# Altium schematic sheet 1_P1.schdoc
size 391 x 276 mm; Symbol: Drawing-Symbol_A4; Device: Drawing-Symbol_A4; Company: 嘉立创EDA; Version: V1.0; Page Size: A4; @Project Name: AD采集模组; @Page Count: 1; @Update Date: 2025-09-16; @Create Date: 2025-08-20; @Schematic Name: Schematic1; @Page No: 1; @Page Name: P1; @Create Time: 00:28:39; @Update Time: 18:31:51; Width: 1500; Height: 1058; Region Start: 1; X Region Count: 6; Y Region Count: 4; Blade Width: 10; Title Block Position: 3; @Board Name: AD采集
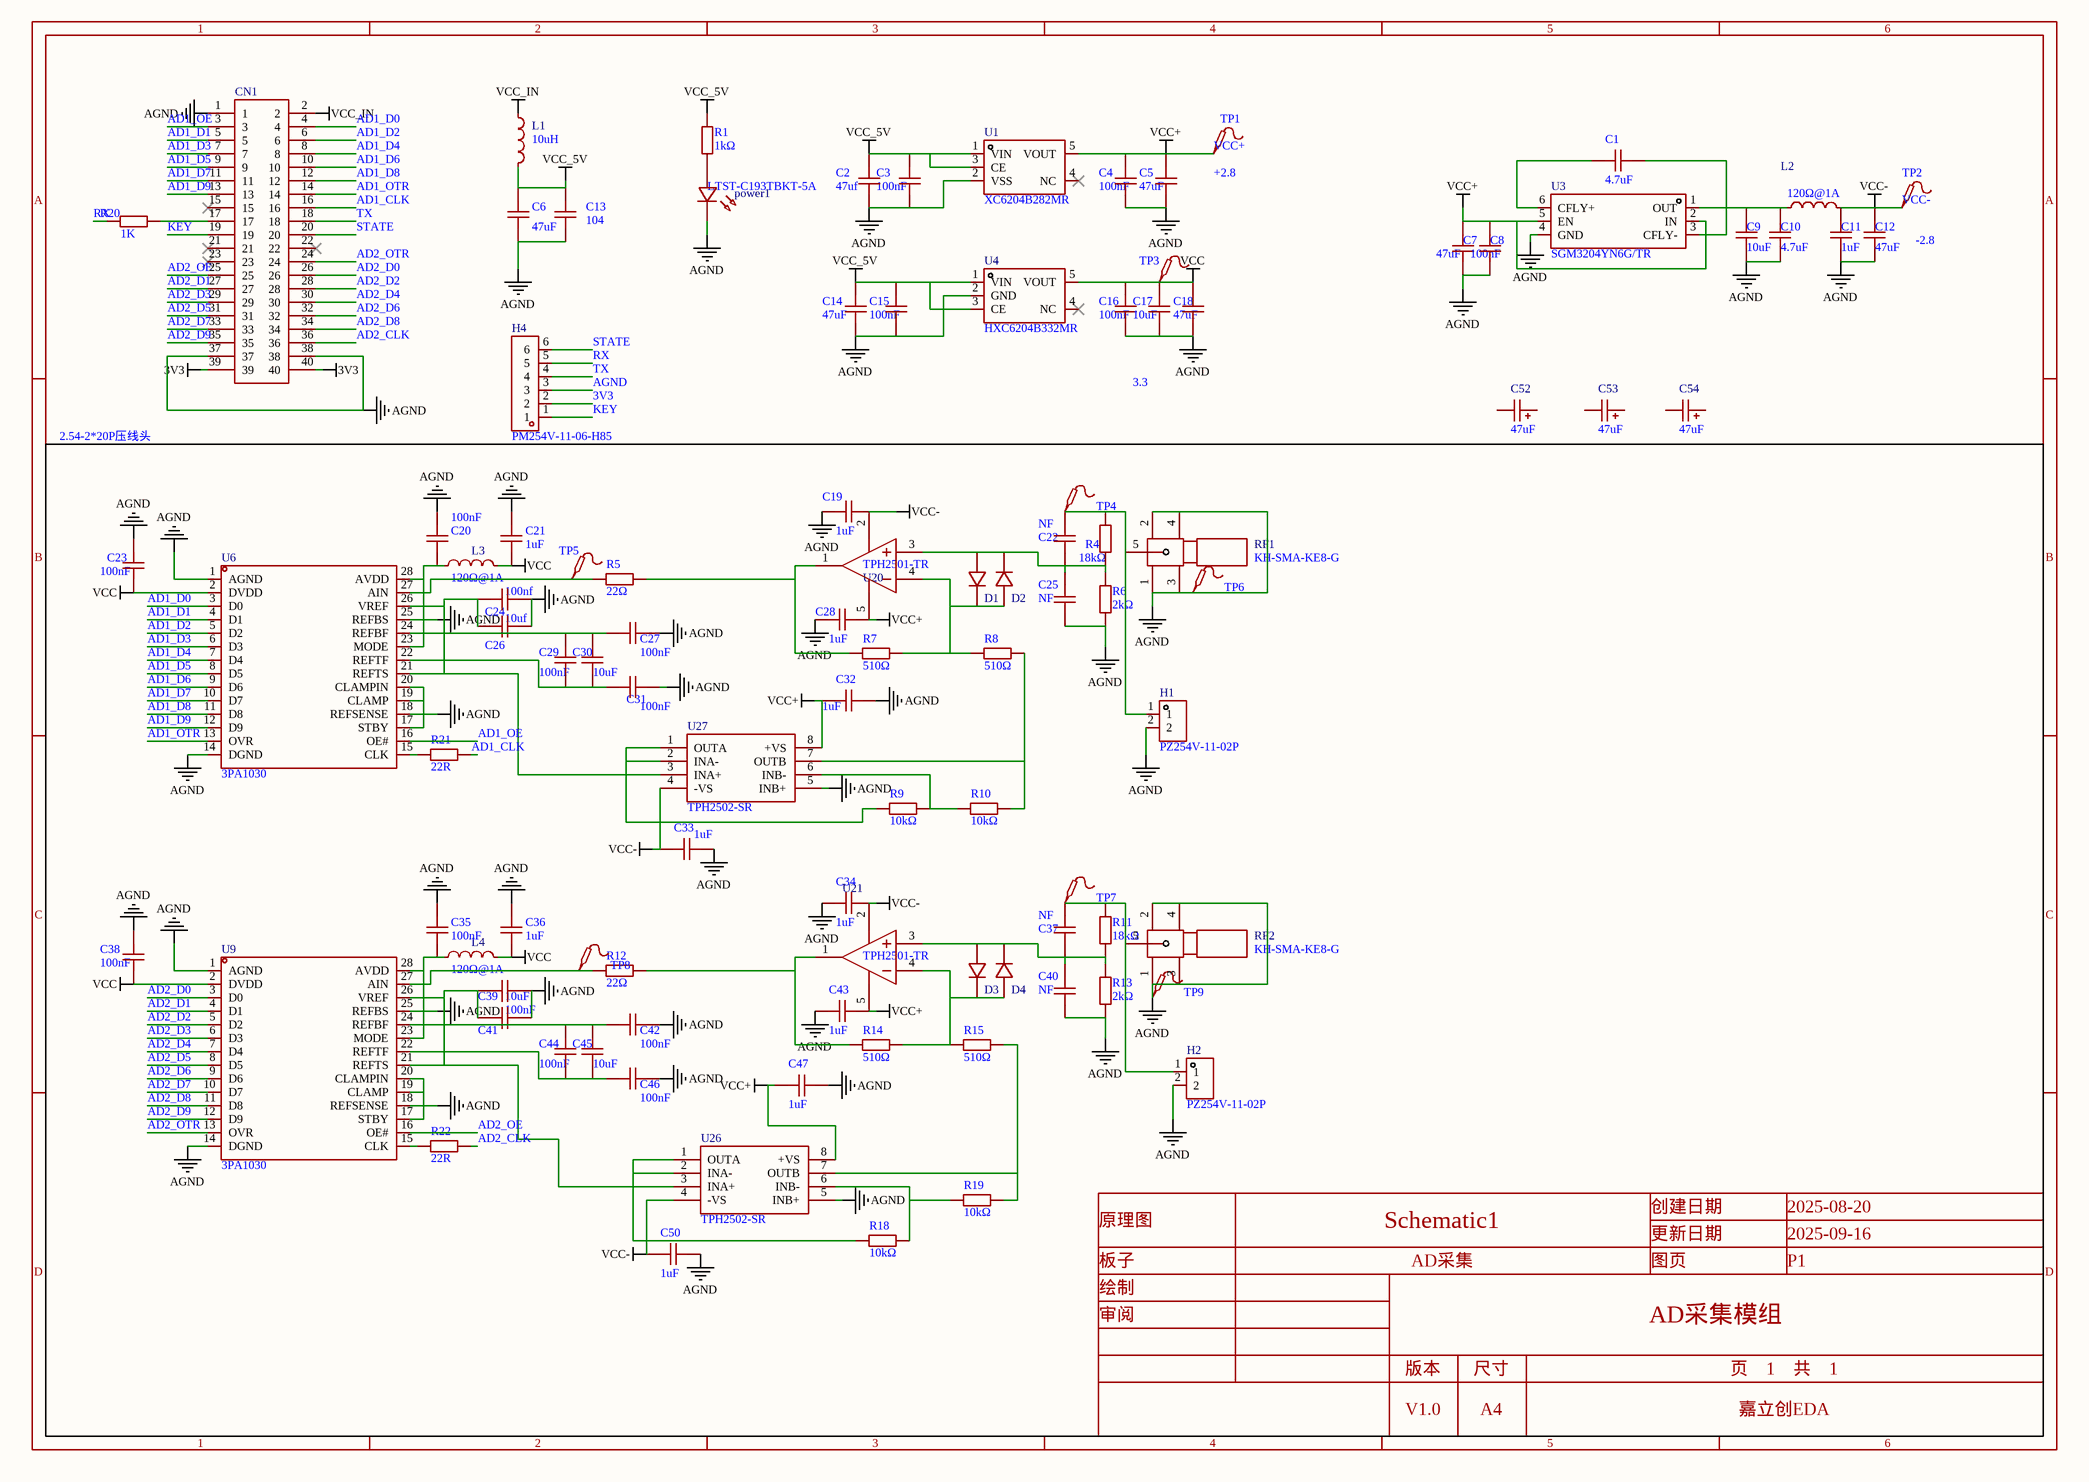
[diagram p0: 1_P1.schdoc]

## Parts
C1  4.7uF  [C0603]
C2  47uf  [C0603]
C3  100nF  [C0603]
C4  100nF  [C0603]
C5  47uF  [C0603]
C6  47uF  [C0603]
C7  47uF  [C0603]
C8  100nF  [C0603]
C9  10uF  [C0603]
C10  4.7uF  [C0603]
C11  1uF  [C0603]
C12  47uF  [C0603]
C13  104  [C0603]
C14  47uF  [C0603]
C15  100nF  [C0603]
C16  100nF  [C0603]
C17  10uF  [C0603]
C18  47uF  [C0603]
C19  1uF  [C0603]
C20  100nF  [C0603]
C21  1uF  [C0603]
C22  NF  [C0603]
C23  100nF  [C0603]
C24  100nf  [C0603]
C25  NF  [C0603]
C26  10uf  [C0603]
C27  100nF  [C0603]
C28  1uF  [C0603]
C29  100nF  [C0603]
C30  10uF  [C0603]
C31  100nF  [C0603]
C32  1uF  [C0603]
C33  1uF  [C0603]
C34  1uF  [C0603]
C35  100nF  [C0603]
C36  1uF  [C0603]
C37  NF  [C0603]
C38  100nF  [C0603]
C39  10uF  [C0603]
C40  NF  [C0603]
C41  100nF  [C0603]
C42  100nF  [C0603]
C43  1uF  [C0603]
C44  100nF  [C0603]
C45  10uF  [C0603]
C46  100nF  [C0603]
C47  1uF  [C0603]
C50  1uF  [C0603]
C52  47uF  [CASE-D_7343]
C53  47uF  [CASE-D_7343]
C54  47uF  [CASE-D_7343]
CN1  2.54-2*20P压线头  [HDR-TH_40P-V-H-R2-P2.54]
D1  1N4148W  [SOD-123F_L2.7-W1.6-LS3.8-RD]  (value not drawn)
D2  1N4148W  [SOD-123F_L2.7-W1.6-LS3.8-RD]  (value not drawn)
D3  1N4148W  [SOD-123F_L2.7-W1.6-LS3.8-RD]  (value not drawn)
D4  1N4148W  [SOD-123F_L2.7-W1.6-LS3.8-RD]  (value not drawn)
H1  PZ254V-11-02P  [HDR-TH_2P-P2.54-V-M]
H2  PZ254V-11-02P  [HDR-TH_2P-P2.54-V-M]
H4  PM254V-11-06-H85  [HDR-TH_6P-P2.54-V-F]
L1  10uH  [L0603]
L2  120Ω@1A  [L0603]
L3  120Ω@1A  [L0603]
L4  120Ω@1A  [L0603]
power1  LTST-C193TBKT-5A  [LED_0603]
R1  1kΩ  [R0603]
R4  18kΩ  [R0603]
R5  22Ω  [R0603]
R6  2kΩ  [R0603]
R7  510Ω  [R0603]
R8  510Ω  [R0603]
R9  10kΩ  [R0603]
R10  10kΩ  [R0603]
R11  18kΩ  [R0603]
R12  22Ω  [R0603]
R13  2kΩ  [R0603]
R14  510Ω  [R0603]
R15  510Ω  [R0603]
R18  10kΩ  [R0603]
R19  10kΩ  [R0603]
R20  1K  [R0603]
R21  22R  [R0603]
R22  22R  [R0603]
RF1  KH-SMA-KE8-G  [CONN-SMD_KH-SMA-KE8-G]
RF2  KH-SMA-KE8-G  [CONN-SMD_KH-SMA-KE8-G]
TP1  (no value)  [Test-Point-0.5mm]
TP2  (no value)  [Test-Point-0.5mm]
TP3  (no value)  [Test-Point-0.5mm]
TP4  (no value)  [Test-Point-0.5mm]
TP5  (no value)  [Test-Point-0.5mm]
TP6  (no value)  [Test-Point-0.5mm]
TP7  (no value)  [Test-Point-0.5mm]
TP8  (no value)  [Test-Point-0.5mm]
TP9  (no value)  [Test-Point-0.5mm]
U1  XC6204B282MR  [SOT-23-5_L2.9-W1.6-P0.95-LS2.8-BR]
U3  SGM3204YN6G/TR  [SOT-23-6_L2.9-W1.6-P0.95-LS2.8-BR]
U4  HXC6204B332MR  [SOT-23-5_L3.0-W1.7-P0.95-LS2.8-BR]
U6  3PA1030  [TSSOP-28_L9.7-W4.4-P0.65-LS6.4-BL]
U9  3PA1030  [TSSOP-28_L9.7-W4.4-P0.65-LS6.4-BL]
U20  TPH2501-TR  [SOT-23-5_L3.0-W1.7-P0.95-LS2.8-BR]
U21  TPH2501-TR  [SOT-23-5_L3.0-W1.7-P0.95-LS2.8-BR]
U26  TPH2502-SR  [SOP-8_L4.9-W3.9-P1.27-LS6.0-BL]
U27  TPH2502-SR  [SOP-8_L4.9-W3.9-P1.27-LS6.0-BL]

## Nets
3V3: CN1.39 CN1.40 H4.2
AGND: C2.1 C3.1 C4.1 C5.1 C6.1 C7.1 C8.1 C9.1 C10.1 C11.1 C12.1 C13.1 C14.1 C15.1 C16.1 C17.1 C18.1 C19.1 C20.2 C21.2 C23.2 C24.2 C25.1 C26.2 C27.2 C28.1 C31.2 C32.2 C33.2 C34.1 C35.2 C36.2 C38.2 C39.2 C40.1 C41.2 C42.2 C43.1 C46.2 C47.2 C50.2 CN1.1 CN1.37 CN1.38 H1.2 H2.2 H4.3 power1.1(C) R6.2 R13.2 RF1.1 RF1.2 RF1.3 RF1.4 RF2.1 RF2.2 RF2.3 RF2.4 TP6.1 TP9.1 U1.2(VSS) U3.4(GND) U4.2(GND) U6.1(AGND) U6.14(DGND) U6.17(STBY) U6.18(REFSENSE) U6.19(CLAMP) U6.20(CLAMPIN) U6.25(REFBS) U9.1(AGND) U9.14(DGND) U9.17(STBY) U9.18(REFSENSE) U9.19(CLAMP) U9.20(CLAMPIN) U9.25(REFBS) U26.5(INB+) U27.5(INB+)
VCC: C16.2 C17.2 C18.2 C21.1 C23.1 C36.1 C38.1 L3.2 L4.2 TP3.1 U4.5(VOUT) U6.2(DVDD) U9.2(DVDD)
VCC+: C4.2 C5.2 C7.2 C8.2 C28.2 C32.1 C43.2 C47.1 TP1.1 U1.5(VOUT) U3.2(IN) U3.5(EN) U20.5(VS+) U21.5(VS+) U26.8(+VS) U27.8(+VS)
VCC-: C11.2 C12.2 C19.2 C33.1 C34.2 C50.1 L2.2 TP2.1 U20.2(VS-) U21.2(VS-) U26.4(-VS) U27.4(-VS)
VCC_5V: C2.2 C3.2 C6.2 C13.2 C14.2 C15.2 L1.2 R1.2 U1.1(VIN) U1.3(CE) U4.1(VIN) U4.3(CE)
VCC_IN: CN1.2 L1.1
AD1_CLK: CN1.16 R21.2
AD1_D0: CN1.4 U6.3(D0)
AD1_D1: CN1.5 U6.4(D1)
AD1_D2: CN1.6 U6.5(D2)
AD1_D3: CN1.7 U6.6(D3)
AD1_D4: CN1.8 U6.7(D4)
AD1_D5: CN1.9 U6.8(D5)
AD1_D6: CN1.10 U6.9(D6)
AD1_D7: CN1.11 U6.10(D7)
AD1_D8: CN1.12 U6.11(D8)
AD1_D9: CN1.13 U6.12(D9)
AD1_OE: CN1.3 U6.16(OE#)
AD1_OTR: CN1.14 U6.13(OVR)
AD2_CLK: CN1.36 R22.2
AD2_D0: CN1.26 U9.3(D0)
AD2_D1: CN1.27 U9.4(D1)
AD2_D2: CN1.28 U9.5(D2)
AD2_D3: CN1.29 U9.6(D3)
AD2_D4: CN1.30 U9.7(D4)
AD2_D5: CN1.31 U9.8(D5)
AD2_D6: CN1.32 U9.9(D6)
AD2_D7: CN1.33 U9.10(D7)
AD2_D8: CN1.34 U9.11(D8)
AD2_D9: CN1.35 U9.12(D9)
AD2_OE: CN1.25 U9.16(OE#)
AD2_OTR: CN1.24 U9.13(OVR)
KEY: CN1.19 H4.1
RX: H4.5 R20.1
STATE: CN1.20 H4.6
TX: CN1.18 H4.4
NetC1_1: C1.1 U3.6(CFLY+)
NetC1_2: C1.2 U3.3(CFLY-)
NetC9_2: C9.2 C10.2 L2.1 U3.1(OUT)
NetC20_1: C20.1 C24.1 C26.1 L3.1 U6.21(REFTS) U6.23(MODE) U6.26(VREF) U6.28(AVDD) U27.3(INA+)
NetC22_1: C22.1 C25.2 D1.2(A) D2.1(K) R4.1 R6.1 U20.3(IN+)
NetC22_2: C22.2 H1.1 R4.2 RF1.5 TP4.1
NetC27_1: C27.1 C29.2 C30.2 U6.24(REFBF)
NetC29_1: C29.1 C30.1 C31.1 U6.22(REFTF)
NetC35_1: C35.1 L4.1 U9.23(MODE) U9.28(AVDD)
NetC37_1: C37.1 C40.2 D3.2(A) D4.1(K) R11.1 R13.1 U21.3(IN+)
NetC37_2: C37.2 H2.1 R11.2 RF2.5 TP7.1
NetC39_1: C39.1 C41.1 U9.21(REFTS) U9.26(VREF) U26.3(INA+)
NetC42_1: C42.1 C44.2 C45.2 U9.24(REFBF)
NetC44_1: C44.1 C45.1 C46.1 U9.22(REFTF)
NetCN1_17: CN1.17 R20.2
NetD1_1: D1.1(K) D2.2(A) R7.2 R8.1 U20.4(IN-)
NetD3_1: D3.1(K) D4.2(A) R14.2 R15.1 U21.4(IN-)
Netpower1_2: power1.2(A) R1.1
NetR5_1: R5.1 TP5.1 U6.27(AIN)
NetR5_2: R5.2 R7.1 U20.1(OUT)
NetR8_2: R8.2 R10.2 U27.7(OUTB)
NetR9_1: R9.1 U27.1(OUTA) U27.2(INA-)
NetR9_2: R9.2 R10.1 U27.6(INB-)
NetR12_1: R12.1 TP8.1 U9.27(AIN)
NetR12_2: R12.2 R14.1 U21.1(OUT)
NetR15_2: R15.2 R19.2 U26.7(OUTB)
NetR18_1: R18.1 U26.1(OUTA) U26.2(INA-)
NetR18_2: R18.2 R19.1 U26.6(INB-)
NetR21_1: R21.1 U6.15(CLK)
NetR22_1: R22.1 U9.15(CLK)

Not connected (* = marked no-connect by the designer): C52 1 2; C53 1 2; C54 1 2; CN1 15* 21* 22* 23*; U1 4(NC)*; U4 4(NC)*

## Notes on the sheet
- (near TP1) +2.8
- -2.8
- 3.3

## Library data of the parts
C1 = CL10A475KA8NQNC: Manufacturer: SAMSUNG(三星); Symbol: Capacitance; Add into BOM: yes; Tolerance: ±10%; Voltage Rating: 25V; Temperature Coefficient: X5R; Channel ID: $1e10147
C2 = CC0603KRX7R9BB104: Manufacturer: YAGEO(国巨); Symbol: Capacitance; Add into BOM: yes; Tolerance: ±10%; Voltage Rating: 50V; Temperature Coefficient: X7R; Channel ID: $1e6548
C3 = CC0603KRX7R9BB104: Manufacturer: YAGEO(国巨); Symbol: Capacitance; Add into BOM: yes; Tolerance: ±10%; Voltage Rating: 50V; Temperature Coefficient: X7R; Channel ID: $1e6572
C4 = CC0603KRX7R9BB104: Manufacturer: YAGEO(国巨); Symbol: Capacitance; Add into BOM: yes; Tolerance: ±10%; Voltage Rating: 50V; Temperature Coefficient: X7R; Channel ID: $1e28875
C5 = CC0603KRX7R9BB104: Manufacturer: YAGEO(国巨); Symbol: Capacitance; Add into BOM: yes; Tolerance: ±10%; Voltage Rating: 50V; Temperature Coefficient: X7R; Channel ID: $1e6836
C6 = GRM188R60J476ME15D: Manufacturer: muRata(村田); Symbol: Capacitance; Add into BOM: yes; Tolerance: ±20%; Voltage Rating: 6.3V; Temperature Coefficient: X5R; Channel ID: $1e11215
C7 = GRM188R60J476ME15D: Manufacturer: muRata(村田); Symbol: Capacitance; Add into BOM: yes; Tolerance: ±20%; Voltage Rating: 6.3V; Temperature Coefficient: X5R; Channel ID: $1e10243
C8 = CC0603KRX7R9BB104: Manufacturer: YAGEO(国巨); Symbol: Capacitance; Add into BOM: yes; Tolerance: ±10%; Voltage Rating: 50V; Temperature Coefficient: X7R; Channel ID: $1e10267
C9 = CL10A106KP8NNNC: Manufacturer: SAMSUNG(三星); Symbol: Capacitance; Add into BOM: yes; Tolerance: ±10%; Voltage Rating: 10V; Temperature Coefficient: X5R; Channel ID: $1e10487
C10 = CL10A475KA8NQNC: Manufacturer: SAMSUNG(三星); Symbol: Capacitance; Add into BOM: yes; Tolerance: ±10%; Voltage Rating: 25V; Temperature Coefficient: X5R; Channel ID: $1e10291
C11 = CL10A105KB8NNNC: Manufacturer: SAMSUNG(三星); Symbol: Capacitance; Add into BOM: yes; Tolerance: ±10%; Voltage Rating: 50V; Temperature Coefficient: X5R; Channel ID: $1e10598
C12 = GRM188R60J476ME15D: Manufacturer: muRata(村田); Symbol: Capacitance; Add into BOM: yes; Tolerance: ±20%; Voltage Rating: 6.3V; Temperature Coefficient: X5R; Channel ID: $1e10574
C13 = CC0603KRX7R9BB104: Manufacturer: YAGEO(国巨); Symbol: Capacitance; Add into BOM: yes; Value: 100nF; Tolerance: ±10%; Voltage Rating: 50V; Temperature Coefficient: X7R; Channel ID: $1e11239
C14 = GRM188R60J476ME15D: Manufacturer: muRata(村田); Symbol: Capacitance; Add into BOM: yes; Tolerance: ±20%; Voltage Rating: 6.3V; Temperature Coefficient: X5R; Channel ID: $1e6476
C15 = CC0603KRX7R9BB104: Manufacturer: YAGEO(国巨); Symbol: Capacitance; Add into BOM: yes; Tolerance: ±10%; Voltage Rating: 50V; Temperature Coefficient: X7R; Channel ID: $1e6500
C16 = CC0603KRX7R9BB104: Manufacturer: YAGEO(国巨); Symbol: Capacitance; Add into BOM: yes; Tolerance: ±10%; Voltage Rating: 50V; Temperature Coefficient: X7R; Channel ID: $1e6908
C17 = CL10A106KP8NNNC: Manufacturer: SAMSUNG(三星); Symbol: Capacitance; Add into BOM: yes; Tolerance: ±10%; Voltage Rating: 10V; Temperature Coefficient: X5R; Channel ID: $1e6932
C18 = GRM188R60J476ME15D: Manufacturer: muRata(村田); Symbol: Capacitance; Add into BOM: yes; Tolerance: ±20%; Voltage Rating: 6.3V; Temperature Coefficient: X5R; Channel ID: $1e6884
C19 = CL10A105KB8NNNC: Manufacturer: SAMSUNG(三星); Symbol: Capacitance; Add into BOM: yes; Tolerance: ±10%; Voltage Rating: 50V; Temperature Coefficient: X5R; Channel ID: $1e2001
C20 = CC0603KRX7R9BB104: Manufacturer: YAGEO(国巨); Symbol: Capacitance; Add into BOM: yes; Tolerance: ±10%; Voltage Rating: 50V; Temperature Coefficient: X7R; Channel ID: $1e3603
C21 = CL10A105KB8NNNC: Manufacturer: SAMSUNG(三星); Symbol: Capacitance; Add into BOM: yes; Tolerance: ±10%; Voltage Rating: 50V; Temperature Coefficient: X5R; Channel ID: $1e3628
C22 C25 C37 C40 = CAP_0603: Symbol: Capacitance; Convert to PCB: yes
C23 = CC0603KRX7R9BB104: Manufacturer: YAGEO(国巨); Symbol: Capacitance; Add into BOM: yes; Tolerance: ±10%; Voltage Rating: 50V; Temperature Coefficient: X7R; Channel ID: $1e4473
C24 = CL10A106KP8NNNC: Manufacturer: SAMSUNG(三星); Symbol: Capacitance; Add into BOM: yes; Tolerance: ±10%; Voltage Rating: 10V; Temperature Coefficient: X5R; Channel ID: $1e3406
C26 = CC0603KRX7R9BB104: Manufacturer: YAGEO(国巨); Symbol: Capacitance; Add into BOM: yes; Tolerance: ±10%; Voltage Rating: 50V; Temperature Coefficient: X7R; Channel ID: $1e3430
C27 = CC0603KRX7R9BB104: Manufacturer: YAGEO(国巨); Symbol: Capacitance; Add into BOM: yes; Tolerance: ±10%; Voltage Rating: 50V; Temperature Coefficient: X7R; Channel ID: $1e3764
C28 = CL10A105KB8NNNC: Manufacturer: SAMSUNG(三星); Symbol: Capacitance; Add into BOM: yes; Tolerance: ±10%; Voltage Rating: 50V; Temperature Coefficient: X5R; Channel ID: $1e2025
C29 = CC0603KRX7R9BB104: Manufacturer: YAGEO(国巨); Symbol: Capacitance; Add into BOM: yes; Tolerance: ±10%; Voltage Rating: 50V; Temperature Coefficient: X7R; Channel ID: $1e3812
C30 = CL10A106KP8NNNC: Manufacturer: SAMSUNG(三星); Symbol: Capacitance; Add into BOM: yes; Tolerance: ±10%; Voltage Rating: 10V; Temperature Coefficient: X5R; Channel ID: $1e3836
C31 = CC0603KRX7R9BB104: Manufacturer: YAGEO(国巨); Symbol: Capacitance; Add into BOM: yes; Tolerance: ±10%; Voltage Rating: 50V; Temperature Coefficient: X7R; Channel ID: $1e3788
C32 = CL10A105KB8NNNC: Manufacturer: SAMSUNG(三星); Symbol: Capacitance; Add into BOM: yes; Tolerance: ±10%; Voltage Rating: 50V; Temperature Coefficient: X5R; Channel ID: $1e22291
C33 = CL10A105KB8NNNC: Manufacturer: SAMSUNG(三星); Symbol: Capacitance; Add into BOM: yes; Tolerance: ±10%; Voltage Rating: 50V; Temperature Coefficient: X5R; Channel ID: $1e22191
C34 = CL10A105KB8NNNC: Manufacturer: SAMSUNG(三星); Symbol: Capacitance; Add into BOM: yes; Tolerance: ±10%; Voltage Rating: 50V; Temperature Coefficient: X5R; Channel ID: $1e11692
C35 = CC0603KRX7R9BB104: Manufacturer: YAGEO(国巨); Symbol: Capacitance; Add into BOM: yes; Tolerance: ±10%; Voltage Rating: 50V; Temperature Coefficient: X7R; Channel ID: $1e12121
C36 = CL10A105KB8NNNC: Manufacturer: SAMSUNG(三星); Symbol: Capacitance; Add into BOM: yes; Tolerance: ±10%; Voltage Rating: 50V; Temperature Coefficient: X5R; Channel ID: $1e12145
C38 = CC0603KRX7R9BB104: Manufacturer: YAGEO(国巨); Symbol: Capacitance; Add into BOM: yes; Tolerance: ±10%; Voltage Rating: 50V; Temperature Coefficient: X7R; Channel ID: $1e12363
C39 = CL10A106KP8NNNC: Manufacturer: SAMSUNG(三星); Symbol: Capacitance; Add into BOM: yes; Tolerance: ±10%; Voltage Rating: 10V; Temperature Coefficient: X5R; Channel ID: $1e12035
C41 = CC0603KRX7R9BB104: Manufacturer: YAGEO(国巨); Symbol: Capacitance; Add into BOM: yes; Tolerance: ±10%; Voltage Rating: 50V; Temperature Coefficient: X7R; Channel ID: $1e12059
C42 = CC0603KRX7R9BB104: Manufacturer: YAGEO(国巨); Symbol: Capacitance; Add into BOM: yes; Tolerance: ±10%; Voltage Rating: 50V; Temperature Coefficient: X7R; Channel ID: $1e12197
C43 = CL10A105KB8NNNC: Manufacturer: SAMSUNG(三星); Symbol: Capacitance; Add into BOM: yes; Tolerance: ±10%; Voltage Rating: 50V; Temperature Coefficient: X5R; Channel ID: $1e11716
C44 = CC0603KRX7R9BB104: Manufacturer: YAGEO(国巨); Symbol: Capacitance; Add into BOM: yes; Tolerance: ±10%; Voltage Rating: 50V; Temperature Coefficient: X7R; Channel ID: $1e12245
C45 = CL10A106KP8NNNC: Manufacturer: SAMSUNG(三星); Symbol: Capacitance; Add into BOM: yes; Tolerance: ±10%; Voltage Rating: 10V; Temperature Coefficient: X5R; Channel ID: $1e12269
C46 = CC0603KRX7R9BB104: Manufacturer: YAGEO(国巨); Symbol: Capacitance; Add into BOM: yes; Tolerance: ±10%; Voltage Rating: 50V; Temperature Coefficient: X7R; Channel ID: $1e12221
C47 = CL10A105KB8NNNC: Manufacturer: SAMSUNG(三星); Symbol: Capacitance; Add into BOM: yes; Tolerance: ±10%; Voltage Rating: 50V; Temperature Coefficient: X5R; Channel ID: $1e11973
C50 = CL10A105KB8NNNC: Manufacturer: SAMSUNG(三星); Symbol: Capacitance; Add into BOM: yes; Tolerance: ±10%; Voltage Rating: 50V; Temperature Coefficient: X5R; Channel ID: $1e11938
C52-C54 = TAJD476K016RNJ: Manufacturer: Kyocera AVX; Add into BOM: yes; Tolerance: ±10%; Rated Voltage: 16V; Equivalent Series Resistance(ESR): 900mΩ@100kHz
CN1 = 2.54-2*20P压线头: Manufacturer: BOOMELE(博穆精密); Symbol: Crimping terminals2*20; Add into BOM: yes; Connector Type: IDC连接器; Pitch: 2.54mm; Holder Type: 三件式(连接器+压排+反折盖)
D1-D4 = 1N4148W_C81598: Manufacturer: ST(先科); Add into BOM: yes; Diode Configuration: 独立式; Voltage - Forward(Vf@If): 1V@50mA; Voltage - DC Reverse(Vr): 75V; Current - Rectified: 150mA; Pd - Power Dissipation: 400mW; Reverse Leakage Current (Ir): 1uA@75V; Reverse Recovery Time (trr): 4ns; Non-Repetitive Peak Forward Surge Current: 1A
H1 H2 = PZ254V-11-02P: Manufacturer: XFCN(兴飞); Add into BOM: yes; Pin Structure: 1x2P; Pitch: 2.54mm; Circluar Pins/Square Pins: 方针
H4 = PM254V-11-06-H85: Manufacturer: XFCN(兴飞); Add into BOM: yes; Holes Structure: 1x6P; Pitch: 2.54mm; Circular Hole / Square Hole: 方孔; Number of Positions: 6P; Current Rating: 3A; Voltage Rating (Max): 250V; Holes Direction: 顶部
L1 = SDFL1608S100KTF: Manufacturer: Sunlord(顺络); Add into BOM: yes; Tolerance: ±10%; Current Rating: 3mA; DC Resistance(DCR): 1.85Ω; Q @ Frequency: 30@2MHz; Frequency - Self Resonant: 17MHz; Channel ID: $1e11153
L2 = 0603WAF1200T5E: Manufacturer: UNI-ROYAL(厚声); Symbol: SDFL1608S100KTF; Add into BOM: yes; Type: 厚膜电阻; Tolerance: ±1%; Power(Watts): 100mW; Overload Voltage (Max): 75V; Temperature Coefficient: ±100ppm/℃; Channel ID: $1e10522
L3 = 0603WAF1200T5E: Manufacturer: UNI-ROYAL(厚声); Symbol: SDFL1608S100KTF; Add into BOM: yes; Type: 厚膜电阻; Tolerance: ±1%; Power(Watts): 100mW; Overload Voltage (Max): 75V; Temperature Coefficient: ±100ppm/℃; Channel ID: $1e3555
L4 = 0603WAF1200T5E: Manufacturer: UNI-ROYAL(厚声); Symbol: SDFL1608S100KTF; Add into BOM: yes; Type: 厚膜电阻; Tolerance: ±1%; Power(Watts): 100mW; Overload Voltage (Max): 75V; Temperature Coefficient: ±100ppm/℃; Channel ID: $1e12097
power1 = LTST-C193TBKT-5A: Manufacturer: LITEON(光宝); Symbol: LED_B; Convert to PCB: yes; Illumination Color: 蓝色; Voltage - Forward(Vf): 2.8V; Power(Watts): 76mW; Forward Current: 5mA; Wavelength - Dominant: 465nm~475nm; Peak Wavelength: 468nm; Lens Color: 无色透明透镜; Luminous Intensity: 15mcd; Viewing Angle: 130°; Channel ID: $1e11077
R1 = 0603WAF1001T5E: Manufacturer: UNI-ROYAL(厚声); Symbol: 电阻; Add into BOM: yes; Tolerance: ±1%; Power(Watts): 100mW; Overload Voltage (Max): 75V; Temperature Coefficient: ±100ppm/℃; Channel ID: $1e11001
R4 = 0603WAF1802T5E: Manufacturer: UNI-ROYAL(厚声); Symbol: 电阻; Add into BOM: yes; Tolerance: ±1%; Power(Watts): 100mW; Voltage-Supply(Max): 75V; Temperature Coefficient: ±100ppm/℃; Channel ID: $1e1242
R5 = 0603WAF220JT5E: Manufacturer: UNI-ROYAL(厚声); Symbol: 电阻; Add into BOM: yes; Tolerance: ±1%; Power(Watts): 100mW; Overload Voltage (Max): 75V; Temperature Coefficient: ±100ppm/℃; Channel ID: $1e3259
R6 = 0603WAF2001T5E: Manufacturer: UNI-ROYAL(厚声); Symbol: 电阻; Add into BOM: yes; Tolerance: ±1%; Power(Watts): 100mW; Voltage-Supply(Max): 75V; Temperature Coefficient: ±100ppm/℃; Channel ID: $1e1266
R7 = 0603WAF5100T5E: Manufacturer: UNI-ROYAL(厚声); Symbol: 电阻; Add into BOM: yes; Tolerance: ±1%; Power(Watts): 100mW; Voltage-Supply(Max): 75V; Temperature Coefficient: ±100ppm/℃; Channel ID: $1e2180
R8 = 0603WAF5100T5E: Manufacturer: UNI-ROYAL(厚声); Symbol: 电阻; Add into BOM: yes; Tolerance: ±1%; Power(Watts): 100mW; Voltage-Supply(Max): 75V; Temperature Coefficient: ±100ppm/℃; Channel ID: $1e2242
R9 = 0603WAF1002T5E: Manufacturer: UNI-ROYAL(厚声); Symbol: 电阻; Add into BOM: yes; Tolerance: ±1%; Power(Watts): 100mW; Voltage-Supply(Max): 75V; Temperature Coefficient: ±100ppm/℃; Channel ID: $1e28661
R10 = 0603WAF1002T5E: Manufacturer: UNI-ROYAL(厚声); Symbol: 电阻; Add into BOM: yes; Tolerance: ±1%; Power(Watts): 100mW; Voltage-Supply(Max): 75V; Temperature Coefficient: ±100ppm/℃; Channel ID: $1e22253
R11 = 0603WAF1802T5E: Manufacturer: UNI-ROYAL(厚声); Symbol: 电阻; Add into BOM: yes; Tolerance: ±1%; Power(Watts): 100mW; Voltage-Supply(Max): 75V; Temperature Coefficient: ±100ppm/℃; Channel ID: $1e11560
R12 = 0603WAF220JT5E: Manufacturer: UNI-ROYAL(厚声); Symbol: 电阻; Add into BOM: yes; Tolerance: ±1%; Power(Watts): 100mW; Overload Voltage (Max): 75V; Temperature Coefficient: ±100ppm/℃; Channel ID: $1e12011
R13 = 0603WAF2001T5E: Manufacturer: UNI-ROYAL(厚声); Symbol: 电阻; Add into BOM: yes; Tolerance: ±1%; Power(Watts): 100mW; Voltage-Supply(Max): 75V; Temperature Coefficient: ±100ppm/℃; Channel ID: $1e11584
R14 = 0603WAF5100T5E: Manufacturer: UNI-ROYAL(厚声); Symbol: 电阻; Add into BOM: yes; Tolerance: ±1%; Power(Watts): 100mW; Voltage-Supply(Max): 75V; Temperature Coefficient: ±100ppm/℃; Channel ID: $1e11768
R15 = 0603WAF5100T5E: Manufacturer: UNI-ROYAL(厚声); Symbol: 电阻; Add into BOM: yes; Tolerance: ±1%; Power(Watts): 100mW; Voltage-Supply(Max): 75V; Temperature Coefficient: ±100ppm/℃; Channel ID: $1e11792
R18 = 0603WAF1002T5E: Manufacturer: UNI-ROYAL(厚声); Symbol: 电阻; Add into BOM: yes; Tolerance: ±1%; Power(Watts): 100mW; Voltage-Supply(Max): 75V; Temperature Coefficient: ±100ppm/℃; Channel ID: $1e22080
R19 = 0603WAF1002T5E: Manufacturer: UNI-ROYAL(厚声); Symbol: 电阻; Add into BOM: yes; Tolerance: ±1%; Power(Watts): 100mW; Voltage-Supply(Max): 75V; Temperature Coefficient: ±100ppm/℃; Channel ID: $1e11816
R20-R22 = Res_0603: Symbol: 电阻; Convert to PCB: yes
RF1 RF2 = KH-SMA-KE8-G: Manufacturer: kinghelm(金航标); Add into BOM: yes; Connector Type: 板端; Interface Type: 内孔; Number of Ports: 1; Interface Length/Height: 8mm; RF Series: SMA; Style: 偏脚
TP1-TP9 = Test-Point: Add into BOM: yes
U1 = XC6204B282MR_C18212677: Manufacturer: TECH PUBLIC(台舟); Add into BOM: yes; Output Type: 固定; Voltage - Supply: 24V; Output Voltage: 2.8V; Output Current: 300mA; Output Configuration: 正极; Number of Outputs: 1
U3 = SGM3204YN6G/TR: Manufacturer: SGMICRO(圣邦微); Add into BOM: yes
U4 = HXC6204B332MR: Manufacturer: HXY MOSFET(华轩阳电子); Add into BOM: yes; Output Type: 固定; Voltage - Supply: 6V; Output Voltage: 3.3V; Output Current: 300mA; Power Supply Rejection Ratio (PSRR): 75dB@(1kHz); Voltage Dropout: 35mV@(100mA)；280mV@(200mA); standby current: 25uA; Noise: 50uVrms; Output Configuration: 正极; Number of Outputs: 1
U6 U9 = 3PA1030: Manufacturer: 3PEAK(思瑞浦); Add into BOM: yes; Resolution(Bits): 10位; Sampling Rate: 50MHz; Voltage - Supply: 2.7V~5.5V; Integral non - linearity: 0.9LSB
U20 U21 = OPA365AIDBVR: Manufacturer: TI(德州仪器); Add into BOM: yes; Number of Channels: 单路; Gain Bandwidth Product: 50MHz; Slew Rate: 25V/us; Ib - Input Bias Current: 0.2pA; Output Current: 65mA
U26 U27 = TPH2502-SR: Manufacturer: 3PEAK(思瑞浦); Add into BOM: yes; Number of Circuits: 双路; Maximum Power Supply Range (Vdd-Vss): 5.5V; Rail to Rail: 轨到轨输入,轨到轨输出; Gain Bandwidth Product(GBP): 120MHz; Voltage - Input Offset(Vos): 50uV; Input Offset Voltage Drift (Vos TC): 2uV/℃; Slew Rate(SR): 180V/us; Current - Input Bias(Ib): 0.3pA; Noise density(eN): 6.5nV/√Hz@1MHz; Common Mode Rejection Ratio (CMRR): 85dB; Quiescent Current: 6.5mA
